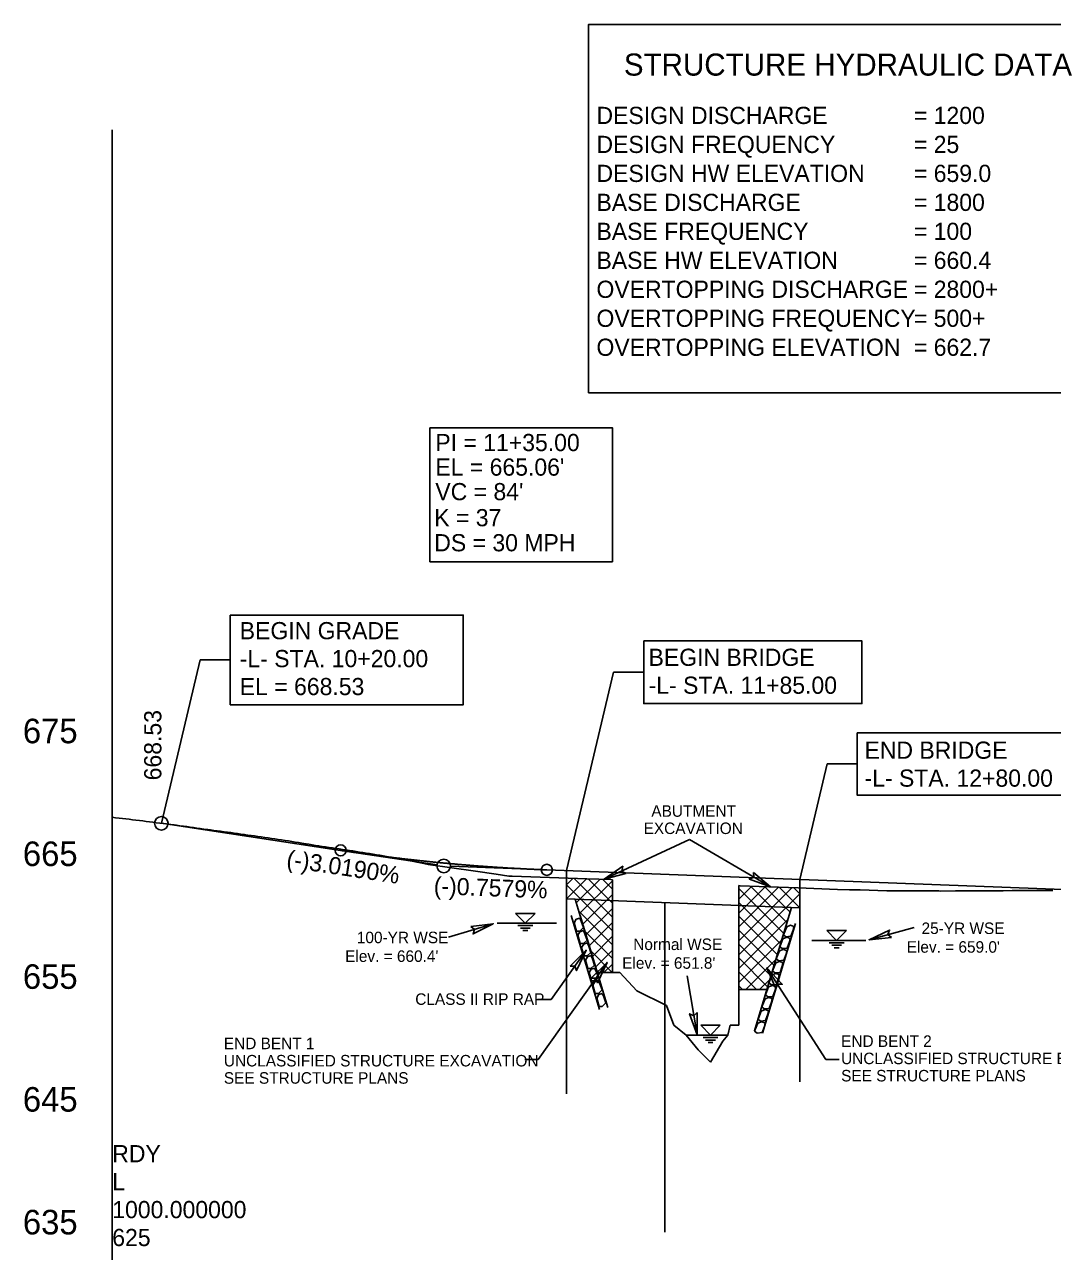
# Model space of a CAD drawing. Extents: x 566644 to 567306, y -52757 to -51996.
# Drawn here: x 566643.7 to 567062.4, y -52496 to -51996.4 of the extents above; entities that cross this region are included whole.
import ezdxf

# ---------------------------------------------------------------- set-up
doc = ezdxf.new("R2010")
doc.units = 0
for name, color, linetype in [('Default', 7, 'Continuous'), ('Prop Dimension', 7, 'Continuous'), ('Prop Dimension Text', 7, 'Continuous'), ('Prop Hatching', 7, 'Continuous'), ('Prop PFL Structure Hydraulic Data Label CELL', 7, 'Continuous'), ('Prop Roadway Bridge', 7, 'Continuous'), ('Prop SS Fill Line', 7, 'Continuous'), ('Prop Terminator CELL', 7, 'Continuous'), ('Sheet Data Field CELL', 7, 'Continuous'), ('Sheet Layout Profile Border', 7, 'Continuous'), ('Sheet Plot Border Inside CELL', 7, 'Continuous'), ('Sheet Plot Border Outside CELL', 7, 'Continuous'), ('Sheet Profile Grid Major CELL', 7, 'Continuous'), ('Sheet Profile Grid Middle CELL', 7, 'Continuous'), ('Sheet Profile Grid Minor CELL', 7, 'Continuous'), ('Sheet Sticker Preliminary CELL', 7, 'Continuous')]:
    doc.layers.add(name, color=color, linetype=linetype)

msp = doc.modelspace()

# ---------------------------------------------------------------- linework, layer by layer
at = {"layer": 'Default'}
for p, q in [((566864.47, -52340.94), (566864.47, -52431.81)), ((566959.47, -52344.54), (566959.47, -52427.01)), ((566851.71, -52358.35), (566843.71, -52358.35)), ((566843.71, -52358.35), (566847.71, -52362.35)), ((566851.71, -52358.35), (566847.71, -52362.35)), ((566904.47, -52353.97), (566904.47, -52488.18)), ((566851.71, -52362.35), (566843.71, -52362.35)), ((566850.71, -52363.35), (566844.71, -52363.35)), ((566847.71, -52362.35), (566847.71, -52362.35)), ((566866.44, -52359.18), (566877.94, -52397.52)), ((566870.01, -52359.2), (566881.26, -52396.72)), ((566941, -52406.13), (566954.16, -52362.26)), ((566944.35, -52407.13), (566957.75, -52362.48)), ((566849.71, -52364.35), (566845.71, -52364.35)), ((566848.71, -52365.35), (566846.71, -52365.35)), ((566978.51, -52365.35), (566970.51, -52365.35)), ((566970.51, -52365.35), (566974.51, -52369.35)), ((566978.51, -52365.35), (566974.51, -52369.35)), ((566986.38, -52369.34), (566964.47, -52369.34)), ((566978.51, -52369.35), (566970.51, -52369.35)), ((566977.51, -52370.35), (566971.51, -52370.35)), ((566976.51, -52371.35), (566972.51, -52371.35)), ((566975.51, -52372.35), (566973.51, -52372.35)), ((566974.51, -52369.35), (566974.51, -52369.35)), ((566913.16, -52407.93), (566930.16, -52407.93)), ((566927.13, -52403.93), (566919.13, -52403.93)), ((566919.13, -52403.93), (566923.13, -52407.93)), ((566927.13, -52407.93), (566919.13, -52407.93)), ((566927.13, -52403.93), (566923.13, -52407.93)), ((566923.13, -52407.93), (566923.13, -52407.93)), ((566926.13, -52408.93), (566920.13, -52408.93)), ((566925.13, -52409.93), (566921.13, -52409.93)), ((566924.13, -52410.93), (566922.13, -52410.93))]:
    msp.add_line(p, q, dxfattribs=at)
for points in [[(566869.85, -52360.29), (566870.51, -52361.6), (566871.38, -52364.15), (566869.88, -52365.55), (566868.57, -52365.55), (566867.62, -52362.15), (566868.47, -52360.76), (566869.85, -52360.29)], [(566957.05, -52363.7), (566956.78, -52365.14), (566955.91, -52367.69), (566953.87, -52367.87), (566952.83, -52367.08), (566954.16, -52363.81), (566955.68, -52363.23), (566957.05, -52363.7)], [(566871.34, -52365.4), (566872, -52366.71), (566872.87, -52369.26), (566871.37, -52370.65), (566870.06, -52370.66), (566869.11, -52367.25), (566869.97, -52365.87), (566871.34, -52365.4)], [(566955.55, -52368.55), (566955.27, -52369.99), (566954.41, -52372.54), (566952.37, -52372.73), (566951.33, -52371.94), (566952.65, -52368.66), (566954.17, -52368.08), (566955.55, -52368.55)], [(566872.86, -52370.41), (566873.52, -52371.72), (566874.39, -52374.27), (566872.89, -52375.66), (566871.58, -52375.67), (566870.64, -52372.27), (566871.49, -52370.88), (566872.86, -52370.41)], [(566954.16, -52373.48), (566953.89, -52374.93), (566953.02, -52377.47), (566950.98, -52377.66), (566949.94, -52376.87), (566951.27, -52373.59), (566952.79, -52373.02), (566954.16, -52373.48)], [(566874.4, -52375.56), (566875.06, -52376.87), (566875.93, -52379.42), (566874.42, -52380.81), (566873.12, -52380.82), (566872.17, -52377.41), (566873.02, -52376.03), (566874.4, -52375.56)], [(566952.58, -52378.38), (566952.31, -52379.82), (566951.44, -52382.37), (566949.4, -52382.56), (566948.36, -52381.76), (566949.69, -52378.49), (566951.21, -52377.91), (566952.58, -52378.38)], [(566875.95, -52380.63), (566876.61, -52381.94), (566877.48, -52384.49), (566875.97, -52385.88), (566874.67, -52385.89), (566873.72, -52382.49), (566874.57, -52381.1), (566875.95, -52380.63)], [(566951.16, -52383.27), (566950.88, -52384.71), (566950.01, -52387.26), (566947.97, -52387.45), (566946.94, -52386.66), (566948.26, -52383.38), (566949.78, -52382.8), (566951.16, -52383.27)], [(566877.44, -52385.7), (566878.1, -52387.01), (566878.97, -52389.56), (566877.46, -52390.96), (566876.16, -52390.96), (566875.21, -52387.56), (566876.06, -52386.17), (566877.44, -52385.7)], [(566949.69, -52388.17), (566949.42, -52389.61), (566948.55, -52392.15), (566946.51, -52392.34), (566945.47, -52391.55), (566946.8, -52388.28), (566948.32, -52387.7), (566949.69, -52388.17)], [(566879.01, -52390.97), (566879.67, -52392.28), (566880.54, -52394.83), (566879.04, -52396.22), (566877.73, -52396.22), (566876.78, -52392.82), (566877.64, -52391.44), (566879.01, -52390.97)], [(566948.23, -52393.06), (566947.95, -52394.5), (566947.09, -52397.05), (566945.05, -52397.24), (566944.01, -52396.44), (566945.33, -52393.17), (566946.85, -52392.59), (566948.23, -52393.06)], [(566946.73, -52398.03), (566946.45, -52399.47), (566945.58, -52402.02), (566943.54, -52402.21), (566942.51, -52401.41), (566943.83, -52398.14), (566945.35, -52397.56), (566946.73, -52398.03)], [(566945.34, -52402.92), (566945.06, -52404.36), (566944.2, -52406.91), (566942.16, -52407.1), (566941.12, -52406.31), (566942.44, -52403.03), (566943.96, -52402.46), (566945.34, -52402.92)]]:
    msp.add_lwpolyline(points, dxfattribs=at)
at = {"layer": 'Prop Dimension'}
for p, q in [((566914.55, -52328.31), (566879.85, -52344.45)), ((566914.55, -52328.31), (566947.62, -52347.58)), ((566816.45, -52368.1), (566834.63, -52362.59)), ((567006.08, -52364.12), (566987.75, -52369.11)), ((566872.51, -52373.37), (566858.25, -52393.45)), ((566881.01, -52378.32), (566852.98, -52417.83)), ((566946.13, -52380.48), (566970.08, -52417.83)), ((566913.65, -52383.74), (566917.67, -52407.87)), ((566858.25, -52393.45), (566852.73, -52393.45)), ((566852.98, -52417.83), (566847.46, -52417.83)), ((566975.6, -52417.83), (566970.08, -52417.83))]:
    msp.add_line(p, q, dxfattribs=at)
at = {"layer": 'Prop Hatching'}
for p, q in [((566864.47, -52346.8), (566867.19, -52344.08)), ((566864.47, -52352.45), (566872.66, -52344.26)), ((566864.47, -52346.8), (566883.17, -52365.49)), ((566867.43, -52344.09), (566883.17, -52359.84)), ((566868.48, -52354.11), (566878.13, -52344.45)), ((566869.78, -52358.46), (566883.18, -52345.06)), ((566873.28, -52344.28), (566883.18, -52354.19)), ((566879.14, -52344.49), (566883.18, -52348.53)), ((566934.68, -52352.56), (566939.9, -52347.34)), ((566934.68, -52358.22), (566945.36, -52347.54)), ((566934.68, -52363.88), (566950.86, -52347.7)), ((566934.68, -52369.53), (566956.36, -52347.85)), ((566934.68, -52348.23), (566952.9, -52366.45)), ((566939.43, -52347.32), (566954.21, -52362.1)), ((566945.3, -52347.54), (566955.51, -52357.75)), ((566951.13, -52347.7), (566959.47, -52356.05)), ((566956.95, -52347.87), (566959.47, -52350.4)), ((566871.09, -52362.81), (566883.18, -52350.72)), ((566934.68, -52375.19), (566959.47, -52350.4)), ((566869.49, -52357.47), (566883.17, -52371.15)), ((566872.4, -52367.16), (566883.18, -52356.38)), ((566934.68, -52353.89), (566951.6, -52370.8)), ((566873.7, -52371.51), (566883.17, -52362.04)), ((566934.68, -52359.54), (566950.29, -52375.15)), ((566934.68, -52380.84), (566954.54, -52360.99)), ((566871.91, -52365.55), (566883.17, -52376.8)), ((566875.01, -52375.86), (566883.17, -52367.7)), ((566934.68, -52365.2), (566948.99, -52379.51)), ((566876.31, -52380.21), (566883.17, -52373.36)), ((566934.68, -52386.5), (566952.12, -52369.07)), ((566934.68, -52370.86), (566947.68, -52383.86)), ((566874.34, -52373.63), (566883.14, -52382.43)), ((566934.68, -52376.52), (566946.38, -52388.21)), ((566937.47, -52389.37), (566949.69, -52377.15)), ((566876.76, -52381.71), (566877.48, -52382.43)), ((566879.75, -52382.43), (566883.17, -52379.02)), ((566934.68, -52382.17), (566941.88, -52389.37)), ((566934.68, -52387.83), (566936.22, -52389.37)), ((566943.13, -52389.37), (566947.27, -52385.23))]:
    msp.add_line(p, q, dxfattribs=at)
at = {"layer": 'Prop Roadway Bridge'}
for p, q in [((566868.02, -52352.59), (566876.98, -52382.43)), ((566946.03, -52389.37), (566956.06, -52355.92)), ((566876.98, -52382.43), (566883.16, -52382.43)), ((566946.03, -52389.37), (566934.68, -52389.37))]:
    msp.add_line(p, q, dxfattribs=at)
at = {"layer": 'Prop SS Fill Line'}
msp.add_line((566860.37, -52362.34), (566836.24, -52362.34), dxfattribs=at)
at = {"layer": 'Prop Terminator CELL'}
for points in [[(566888.66, -52342.06), (566879.85, -52344.45), (566887.38, -52339.19), (566887.01, -52341.12)], [(566940.62, -52341.71), (566947.62, -52347.58), (566938.99, -52344.41), (566940.79, -52343.6)], [(566825.57, -52363.71), (566834.63, -52362.59), (566826.44, -52366.74), (566827.07, -52364.88)], [(566996.84, -52368.24), (566987.75, -52369.11), (566996.06, -52365.19), (566995.37, -52367.03)], [(566866.03, -52379.81), (566872.51, -52373.37), (566868.57, -52381.67), (566867.93, -52379.81)], [(566874.54, -52384.77), (566881.01, -52378.32), (566877.08, -52386.63), (566876.44, -52384.77)], [(566949.69, -52388.89), (566946.13, -52380.48), (566952.36, -52387.23), (566950.4, -52387.13)], [(566917.72, -52398.74), (566917.67, -52407.87), (566914.61, -52399.21), (566916.37, -52400.08)]]:
    msp.add_lwpolyline(points, close=True, dxfattribs=at)
at = {"layer": 'Sheet Layout Profile Border'}
msp.add_line((566679.47, -52539.34), (566679.47, -52039.34), dxfattribs=at)
at = {"layer": 'Sheet Plot Border Inside CELL'}
for centre in [(566772.47, -52332.71), (566856.47, -52340.64)]:
    msp.add_circle(centre, 2.25, dxfattribs=at)
at = {"layer": 'Sheet Plot Border Outside CELL'}
for points in [[(566873.41, -52146.43), (567098.41, -52146.43), (567098.41, -51996.43), (566873.41, -51996.43)], [(566808.85, -52160.62), (566883.17, -52160.62), (566883.17, -52215.17), (566808.85, -52215.17)], [(566727.56, -52236.87), (566822.41, -52236.87), (566822.41, -52273.44), (566727.56, -52273.44)], [(566895.94, -52247.41), (566984.8, -52247.41), (566984.8, -52272.94), (566895.94, -52272.94)], [(566982.92, -52284.81), (567076.24, -52284.81), (567076.24, -52310.24), (566982.92, -52310.24)]]:
    msp.add_lwpolyline(points, close=True, dxfattribs=at)
at = {"layer": 'Sheet Profile Grid Major CELL'}
for p, q in [((566699.47, -52321.69), (566715.28, -52255.16)), ((566715.28, -52255.16), (566727.56, -52255.16)), ((566864.47, -52340.94), (566883.66, -52260.18)), ((566883.66, -52260.18), (566895.94, -52260.18)), ((566959.47, -52344.54), (566970.64, -52297.53)), ((566970.64, -52297.53), (566982.92, -52297.53)), ((566772.47, -52332.71), (566811.75, -52338.64)), ((566856.47, -52340.64), (566817.22, -52339.15))]:
    msp.add_line(p, q, dxfattribs=at)
for centre in [(566699.47, -52321.69), (566814.47, -52339.05)]:
    msp.add_circle(centre, 2.75, dxfattribs=at)
at = {"layer": 'Sheet Profile Grid Middle CELL'}
for p, q in [((566699.47, -52321.69), (566772.47, -52332.71)), ((566856.47, -52340.64), (567076.01, -52348.96)), ((566864.47, -52352.45), (566959.47, -52356.05))]:
    msp.add_line(p, q, dxfattribs=at)
msp.add_spline([(566772.47, -52332.71), (566774.15, -52332.96), (566775.83, -52333.21), (566777.51, -52333.45), (566779.19, -52333.69), (566780.87, -52333.93), (566782.55, -52334.16), (566784.23, -52334.39), (566785.91, -52334.62), (566787.59, -52334.84), (566789.27, -52335.06), (566790.95, -52335.27), (566792.63, -52335.48), (566794.31, -52335.69), (566795.99, -52335.89), (566797.67, -52336.09), (566799.35, -52336.28), (566801.03, -52336.47), (566802.71, -52336.66), (566804.39, -52336.84), (566806.07, -52337.02), (566807.75, -52337.2), (566809.43, -52337.37), (566811.11, -52337.54), (566812.79, -52337.7), (566814.47, -52337.86), (566816.15, -52338.02), (566817.83, -52338.17), (566819.51, -52338.32), (566821.19, -52338.47), (566822.87, -52338.61), (566824.55, -52338.75), (566826.23, -52338.88), (566827.91, -52339.01), (566829.59, -52339.14), (566831.27, -52339.26), (566832.95, -52339.38), (566834.63, -52339.49), (566836.31, -52339.6), (566837.99, -52339.71), (566839.67, -52339.82), (566841.35, -52339.92), (566843.03, -52340.01), (566844.71, -52340.1), (566846.39, -52340.19), (566848.07, -52340.28), (566849.75, -52340.36), (566851.43, -52340.43), (566853.11, -52340.51), (566854.79, -52340.58), (566856.47, -52340.64)], degree=3, dxfattribs=at)
at = {"layer": 'Sheet Sticker Preliminary CELL'}
for p, q in [((566841.06, -52343.18), (566842.31, -52343.22)), ((566842.31, -52343.22), (566865.14, -52344.02)), ((566865.14, -52344.02), (566872.7, -52344.26)), ((566872.7, -52344.26), (566882.57, -52344.61)), ((566882.57, -52344.61), (566883.18, -52344.64)), ((566883.18, -52344.64), (566883.16, -52382.43)), ((566935.28, -52347.15), (566934.68, -52346.96)), ((566934.68, -52346.96), (566934.68, -52389.33)), ((566935.28, -52347.15), (566942.93, -52347.47)), ((566942.93, -52347.47), (566958.88, -52347.92)), ((566958.88, -52347.92), (566974.9, -52348.63)), ((566974.9, -52348.63), (566979.73, -52348.78)), ((566979.73, -52348.78), (566984.03, -52348.81)), ((566984.03, -52348.81), (566995.01, -52349.14)), ((566995.01, -52349.14), (567016.11, -52349.23)), ((567016.11, -52349.23), (567016.97, -52349.25)), ((567016.97, -52349.25), (567022.94, -52349.13)), ((567022.94, -52349.13), (567042.02, -52349.15)), ((567042.02, -52349.15), (567042.34, -52349.15)), ((567042.34, -52349.15), (567045.96, -52349.11)), ((567045.96, -52349.11), (567060.37, -52349.07)), ((567060.37, -52349.07), (567061.48, -52349.07)), ((567061.48, -52349.07), (567062.58, -52349.07)), ((566883.16, -52382.43), (566886.16, -52382.43)), ((566886.16, -52382.43), (566893.16, -52389.93)), ((566893.16, -52389.93), (566905.16, -52395.93)), ((566934.68, -52389.33), (566934.68, -52403.95)), ((566905.16, -52395.93), (566908.16, -52403.93)), ((566908.16, -52403.93), (566913.16, -52407.93)), ((566913.16, -52407.93), (566918.16, -52413.93)), ((566928.16, -52410.43), (566930.16, -52407.93)), ((566930.16, -52407.93), (566931.16, -52403.93)), ((566931.16, -52403.93), (566934.68, -52403.95)), ((566923.16, -52418.93), (566928.16, -52410.43)), ((566918.16, -52413.93), (566923.16, -52418.93))]:
    msp.add_line(p, q, dxfattribs=at)
msp.add_lwpolyline([(566679.47, -52319.23), (566680.85, -52319.39), (566682.23, -52319.56), (566683.61, -52319.73), (566684.99, -52319.89), (566686.37, -52320.06), (566687.75, -52320.23), (566689.13, -52320.4), (566690.51, -52320.57), (566691.89, -52320.74), (566693.27, -52320.91), (566694.65, -52321.09), (566696.03, -52321.26), (566697.41, -52321.43), (566698.79, -52321.6), (566700.17, -52321.78), (566701.55, -52321.95), (566702.92, -52322.13), (566703.29, -52322.17), (566704.3, -52322.28), (566704.68, -52322.32), (566705.68, -52322.46), (566707.06, -52322.65), (566708.44, -52322.85), (566709.82, -52323.04), (566711.2, -52323.24), (566712.58, -52323.43), (566713.96, -52323.63), (566715.34, -52323.83), (566716.72, -52324.03), (566718.37, -52324.27), (566719.48, -52324.41), (566720.86, -52324.58), (566722.24, -52324.76), (566723.62, -52324.94), (566725, -52325.12), (566726.38, -52325.31), (566727.76, -52325.49), (566729.13, -52325.68), (566730.51, -52325.87), (566731.89, -52326.07), (566733.27, -52326.26), (566733.87, -52326.35), (566734.71, -52326.48), (566736.03, -52326.66), (566737.41, -52326.85), (566738.79, -52327.04), (566740.17, -52327.24), (566741.55, -52327.44), (566742.93, -52327.64), (566744.31, -52327.84), (566745.69, -52328.04), (566747.07, -52328.25), (566748.45, -52328.46), (566749.83, -52328.67), (566751.21, -52328.88), (566752.59, -52329.1), (566753.97, -52329.31), (566755.34, -52329.53), (566756.72, -52329.75), (566758.35, -52330.02), (566759.48, -52330.21), (566760.86, -52330.45), (566762.24, -52330.68), (566763.62, -52330.92), (566764.12, -52331.01), (566765, -52331.13), (566766.38, -52331.33), (566767.76, -52331.52), (566769.14, -52331.72), (566770.52, -52331.92), (566771.9, -52332.12), (566773.28, -52332.32), (566774.66, -52332.53), (566776.04, -52332.74), (566777.42, -52332.95), (566778.8, -52333.16), (566780.18, -52333.38), (566781.55, -52333.6), (566782.93, -52333.82), (566784.31, -52334.04), (566785.69, -52334.26), (566787.07, -52334.49), (566788.45, -52334.71), (566789.83, -52334.94), (566791.21, -52335.18), (566792.59, -52335.41), (566794.02, -52335.66), (566795.35, -52335.89), (566796.73, -52336.16), (566798.11, -52336.42), (566799.49, -52336.69), (566800.87, -52336.96), (566802.25, -52337.23), (566803.63, -52337.51), (566805.01, -52337.78), (566806.39, -52338.06), (566808.12, -52338.4), (566827.43, -52341.17), (566835.83, -52342.44), (566841.06, -52343.18)], dxfattribs=at)

# ---------------------------------------------------------------- texts
at = {"layer": 'Default'}
for s, height, p in [('25-YR WSE', 4.687, (567009.1, -52366.76)), ('100-YR WSE', 4.688, (566779.09, -52370.51)), ('Normal WSE', 4.687, (566891.67, -52373.29)), ("Elev. = 660.4'", 4.6875, (566774.33, -52378.12)), ("Elev. = 659.0'", 4.6875, (567003.04, -52374.37)), ("Elev. = 651.8'", 4.6875, (566887.15, -52380.91))]:
    msp.add_text(s, height=height, rotation=359.9999, dxfattribs=at).set_placement(p)
at = {"layer": 'Prop Dimension Text'}
for s, height, p in [('ABUTMENT', 4.687, (566899.04, -52319.02)), ('EXCAVATION', 4.687, (566895.89, -52326.05)), ('CLASS II RIP RAP', 4.6867, (566802.88, -52395.61)), ('END BENT 2', 4.687, (566976.33, -52412.73)), ('END BENT 1', 4.687, (566724.93, -52413.66)), ('UNCLASSIFIED STRUCTURE EXCAVATION', 4.6867, (566724.93, -52420.69)), ('UNCLASSIFIED STRUCTURE EXCAVATION', 4.6867, (566976.33, -52419.76)), ('SEE STRUCTURE PLANS', 4.6867, (566724.93, -52427.72)), ('SEE STRUCTURE PLANS', 4.6867, (566976.33, -52426.79))]:
    msp.add_text(s, height=height, rotation=359.9999, dxfattribs=at).set_placement(p)
at = {"layer": 'Prop PFL Structure Hydraulic Data Label CELL'}
for s, height, p in [('STRUCTURE HYDRAULIC DATA', 9, (566887.84, -52017.23)), ('DESIGN DISCHARGE', 6.9999, (566876.69, -52036.93)), ('= 1200    ', 7, (567005.97, -52036.93)), ('DESIGN FREQUENCY', 6.9999, (566876.69, -52048.73)), ('= 25 ', 7, (567005.97, -52048.73)), ('DESIGN HW ELEVATION', 6.9999, (566876.69, -52060.53)), ('= 659.0   ', 7, (567005.97, -52060.53)), ('BASE DISCHARGE', 6.9999, (566876.69, -52072.33)), ('= 1800    ', 7, (567005.97, -52072.33)), ('BASE FREQUENCY', 6.9999, (566876.69, -52084.13)), ('= 100', 7, (567005.97, -52084.13)), ('BASE HW ELEVATION', 6.9999, (566876.69, -52095.93)), ('= 660.4   ', 7, (567005.97, -52095.93)), ('OVERTOPPING DISCHARGE', 6.9999, (566876.69, -52107.73)), ('= 2800+   ', 7, (567005.97, -52107.73)), ('OVERTOPPING FREQUENCY', 6.9999, (566876.69, -52119.53)), ('= 500+', 7, (567005.97, -52119.53)), ('OVERTOPPING ELEVATION', 6.9999, (566876.69, -52131.33)), ('= 662.7   ', 7, (567005.97, -52131.33))]:
    msp.add_text(s, height=height, dxfattribs=at).set_placement(p)
at = {"layer": 'Sheet Data Field CELL'}
for s, rotation, p in [('(-)3.0190%', 351.416, (566750.11, -52339.45)), ('(-)0.7579%', 357.8299, (566810.33, -52350.53))]:
    msp.add_text(s, height=7, rotation=rotation, dxfattribs=at).set_placement(p)
at = {"layer": 'Sheet Layout Profile Border'}
for s, p in [('RDY', (566679.47, -52459.72)), ('L', (566679.47, -52471.09)), ('1000.000000', (566679.47, -52482.47)), ('625', (566679.47, -52493.84))]:
    msp.add_text(s, height=7, dxfattribs=at).set_placement(p)
at = {"layer": 'Sheet Plot Border Inside CELL'}
for s, p in [("VC = 84'", (566811.06, -52190.13)), ('K = 37', (566810.62, -52200.73)), ('DS = 30 MPH', (566810.62, -52210.93))]:
    msp.add_text(s, height=7, dxfattribs=at).set_placement(p)
at = {"layer": 'Sheet Profile Grid Major CELL'}
for s, p in [('PI = 11+35.00', (566811.06, -52170.13)), ("EL = 665.06'", (566811.06, -52180.13)), ('BEGIN GRADE', (566731.4, -52246.74)), ('-L- STA. 10+20.00', (566731.4, -52258.11)), ('BEGIN BRIDGE', (566897.91, -52257.58)), ('EL = 668.53', (566731.4, -52269.49)), ('-L- STA. 11+85.00', (566897.91, -52268.95)), ('END BRIDGE', (566985.86, -52295.4)), ('-L- STA. 12+80.00', (566985.86, -52306.78))]:
    msp.add_text(s, height=7, dxfattribs=at).set_placement(p)
msp.add_text('668.53', height=7, rotation=90, dxfattribs=at).set_placement((566699.47, -52304.19))
at = {"layer": 'Sheet Profile Grid Minor CELL'}
for s, p in [('675', (566643.06, -52289.09)), ('665', (566643.06, -52339.09)), ('655', (566643.06, -52389.09)), ('645', (566643.06, -52439.09)), ('635', (566643.06, -52489.09))]:
    msp.add_text(s, height=10, dxfattribs=at).set_placement(p)

doc.saveas('drawing.dxf')
